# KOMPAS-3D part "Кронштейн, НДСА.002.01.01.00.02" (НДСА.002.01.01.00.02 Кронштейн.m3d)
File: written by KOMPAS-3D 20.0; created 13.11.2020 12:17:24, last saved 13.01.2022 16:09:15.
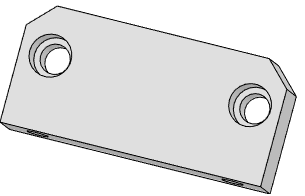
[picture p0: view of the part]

Document properties: Автор: 111; Полное имя файла: C:\Users\korychko\Desktop\PLM\НДСА.002.01.01.00.02 Кронштейн.m3d

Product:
- Part/product: Кронштейн  | designation НДСА.002.01.01.00.02
    Материал: Д16  ГОСТ 4784-97 (density 2800 kg/m3)
    Масса: 0.268074
    additional columns: <item xmlns="http://appius.ru/pdm" xmlns:xs="http://www.w3.org/2001/XMLSchema" x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; <item xmlns="http://appius.ru/pdm" xmlns:xs="http://www.w3.org/2001/XMLSchema" x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; <item xmlns="http://appius.ru/pdm" xmlns:xs="http://www.w3.org/2001/XMLSchema" x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
    source file: НДСА.002.01.01.00.02 Кронштейн.cdw

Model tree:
1. Эскиз:1
2. Элемент выдавливания:1
     Расстояние 1 = 20
3. Элемент выдавливания:5  (with: Элемент выдавливания:1)
     Расстояние 2 = 0.5
4. Элемент выдавливания:6  (with: Элемент выдавливания:1)
     Расстояние 2 = 0.5
5. Элемент выдавливания:7  (with: Элемент выдавливания:1)
     Расстояние 2 = 0.5
6. Фаска:1  (with: Элемент выдавливания:7)
     Угол = 45; Длина 1 = 10; Длина 2 = 10
7. Эскиз:19  (with: Элемент выдавливания:1, Элемент выдавливания:2)
8. Отверстие:1  (with: Элемент выдавливания:1, Элемент выдавливания:6)  (labels: M8)
     Глубина выреза = 19; Диаметр отверстия = 6.64684; Угол конуса дна = 118; Расстояние 1 = 13.5; Расстояние 2 = -10; Диаметр зенковки = 8.64684; Глубина зенковки = 1; Угол зенковки = 90
9. M8  (labels: M8; cil0_24705-2004 coarse)
     Длина резьбы = 16; Шаг резьбы = 1.25; Номинальный диаметр резьбы = 8
10. Отверстие:2  (with: Элемент выдавливания:1, Элемент выдавливания:6, M8)  (labels: M8; cil0_24705-2004 coarse)
     Глубина выреза = 19; Диаметр отверстия = 6.64684; Угол конуса дна = 118; Расстояние 1 = 93.5; Расстояние 2 = -10; Диаметр зенковки = 8.64684; Глубина зенковки = 1; Угол зенковки = 90; Длина резьбы = 16; Шаг резьбы = 1.25; Номинальный диаметр резьбы = 8
11. Эскиз:20  (with: Элемент выдавливания:1)
12. Элемент выдавливания:8  (labels: Д16  ГОСТ 4784-97)
     Расстояние 1 = 10

Referenced files in C:\Users\korychko\Desktop\PLM\: НДСА.002.01.01.00.00 Каркас.a3d
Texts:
  НДСА.002.01.01.00.02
